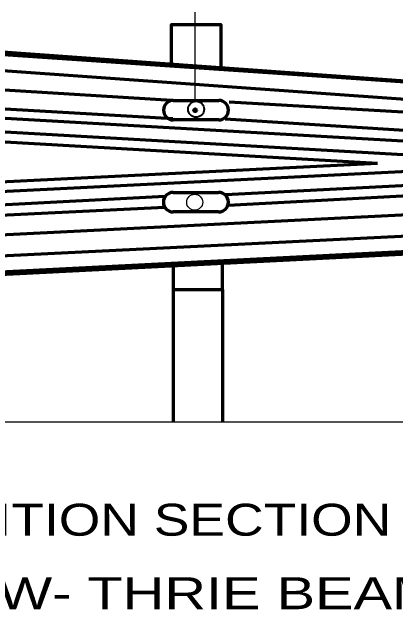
# Model space of a CAD drawing. Extents: x 895.6 to 930.4, y -2278.6 to -2254.7.
# Drawn here: x 915.85 to 919.51, y -2265.84 to -2260.04 of the extents above; entities that cross this region are included whole.
import ezdxf
from ezdxf.enums import TextEntityAlignment as Align

# ---------------------------------------------------------------- set-up
doc = ezdxf.new("R2010")
doc.units = 0
doc.header["$LTSCALE"] = 0.051
doc.header["$PDMODE"] = 32
doc.header["$PDSIZE"] = 0.0255
doc.layers.add('1', color=7, linetype='Continuous', lineweight=70)

msp = doc.modelspace()

# ---------------------------------------------------------------- linework, layer by layer
at = {"layer": '1', "lineweight": 25}
for p, q in [((917.59408, -2260.87842), (917.59408, -2260.04475)), ((911.88058, -2263.95558), (922.89942, -2263.95558))]:
    msp.add_line(p, q, dxfattribs=at)
at = {"layer": '1'}
for p, q in [((913.85217, -2260.28858), (921.30733, -2260.82175)), ((913.85217, -2260.31833), (921.30483, -2260.82608)), ((913.85217, -2260.46825), (921.30733, -2260.99608)), ((917.41958, -2260.88975), (913.85217, -2260.67058)), ((917.37925, -2261.06158), (913.85217, -2260.86133)), ((917.38317, -2260.88867), (917.81808, -2260.88867)), ((921.30733, -2261.09925), (917.91892, -2260.90392)), ((921.30733, -2261.37642), (913.84675, -2260.95042)), ((921.09808, -2261.49383), (913.83925, -2261.08083)), ((917.81808, -2261.07358), (917.38317, -2261.07358)), ((921.30733, -2261.28567), (917.88075, -2261.06475)), ((919.33525, -2261.48833), (913.83358, -2261.17408)), ((919.33525, -2261.48833), (913.83642, -2261.75992)), ((921.09808, -2261.49383), (913.84075, -2261.85333)), ((921.30733, -2261.61683), (917.88308, -2261.78708)), ((921.30733, -2261.70483), (917.90675, -2261.89108)), ((917.30425, -2261.80542), (913.84792, -2261.98625)), ((917.38217, -2261.76733), (917.81717, -2261.76733)), ((921.30733, -2261.89558), (913.85217, -2262.26483)), ((917.30425, -2261.90967), (913.85217, -2262.07408)), ((917.81717, -2261.95217), (917.38217, -2261.95217)), ((921.30733, -2262.09933), (913.85217, -2262.46558)), ((913.85217, -2262.61567), (921.30483, -2262.24375)), ((921.39667, -2262.26483), (913.85217, -2262.64575)), ((917.38383, -2262.69075), (917.38383, -2263.94725)), ((917.85525, -2262.69075), (917.85525, -2263.94725))]:
    msp.add_line(p, q, dxfattribs=at)
for points in [[(917.36725, -2260.54875), (917.36725, -2260.16408), (917.83858, -2260.16408), (917.83858, -2260.56283)], [(917.38383, -2262.46725), (917.38383, -2262.69075), (917.85525, -2262.69075), (917.85525, -2262.44333)]]:
    msp.add_lwpolyline(points, dxfattribs=at)
at = {"layer": '1', "lineweight": 40}
msp.add_circle((917.60122, -2260.97174), 0.07627, dxfattribs=at)
at = {"layer": '1', "lineweight": 25}
msp.add_circle((917.58821, -2261.85954), 0.07627, dxfattribs=at)
at = {"layer": '1'}
for centre, start, end in [((917.384, -2260.98023), 90, 270), ((917.81814, -2260.98023), 270, 90), ((917.38306, -2261.85887), 90, 270), ((917.8172, -2261.85887), 270, 90)]:
    msp.add_arc(centre, 0.09303, start, end, dxfattribs=at)
msp.add_point((917.59375, -2260.98183), dxfattribs=at)

# ---------------------------------------------------------------- texts
for s, width, p in [('TRANSITION SECTION DETAIL', 1.25, (917.67987, -2265.04192)), ('(W- THRIE BEAM )', 1.35, (917.89642, -2265.74367))]:
    msp.add_text(s, height=0.3052, dxfattribs=dict(at, width=width)).set_placement(p, align=Align.CENTER)

doc.saveas('drawing.dxf')
